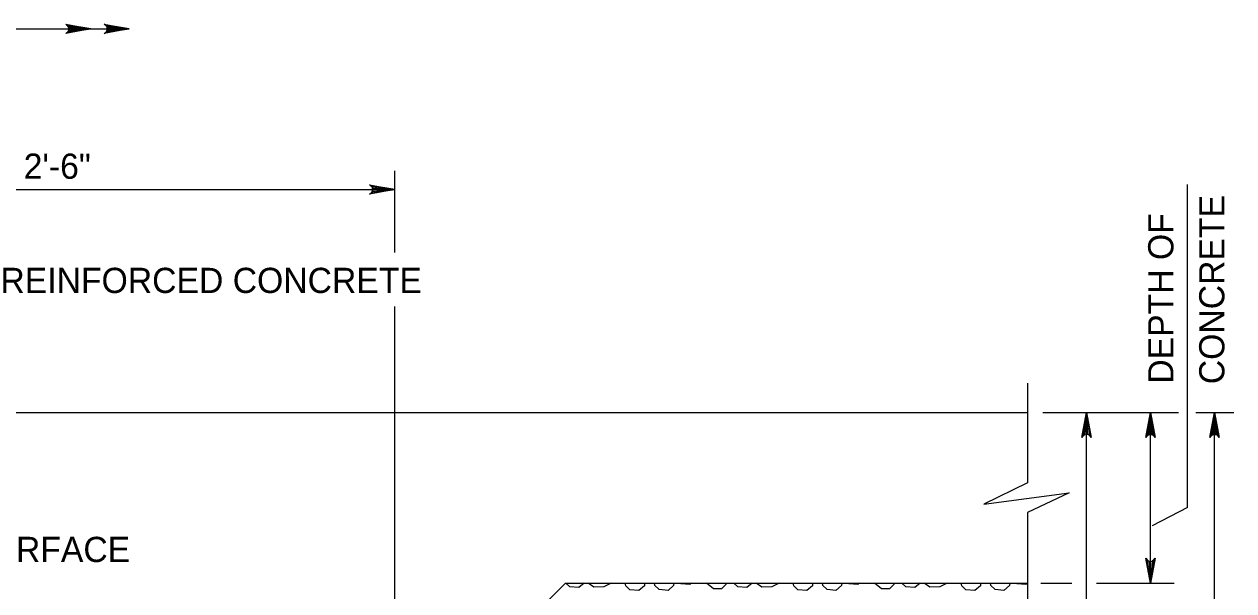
# Model space of a CAD drawing. Extents: x 638079 to 640019, y 297691 to 298879.
# Drawn here: x 639404.5 to 639548.5, y 298555.9 to 298623.3 of the extents above; entities that cross this region are included whole.
import ezdxf

# ---------------------------------------------------------------- set-up
doc = ezdxf.new("R2010")
doc.units = 0
doc.layers.add('1', color=7, linetype='Continuous')

msp = doc.modelspace()

# ---------------------------------------------------------------- linework, layer by layer
at = {"layer": '1'}
for p, q in [((639341.94, 298622.76), (639417.03, 298622.76)), ((639448.62, 298596.16), (639448.62, 298605.88)), ((639542.96, 298565.79), (639542.96, 298604.23)), ((639265.74, 298603.66), (639448.62, 298603.66)), ((639448.62, 298539.46), (639448.62, 298589.72)), ((639523.91, 298580.62), (639523.91, 298568.73)), ((639341.94, 298577.12), (639523.91, 298577.12)), ((639525.72, 298577.12), (639541.89, 298577.12)), ((639530.92, 298533.94), (639530.92, 298577.12)), ((639538.54, 298556.8), (639538.54, 298577.12)), ((639543.95, 298577.12), (639548.46, 298577.12)), ((639546.16, 298506), (639546.16, 298577.12)), ((639523.91, 298565.21), (639523.91, 298531.8)), ((639542.96, 298565.79), (639538.73, 298563.63)), ((639448.62, 298536.49), (639468.94, 298556.8)), ((639468.94, 298556.8), (639523.92, 298556.8)), ((639525.48, 298556.8), (639529.18, 298556.8)), ((639532.13, 298556.8), (639541.36, 298556.8))]:
    msp.add_line(p, q, dxfattribs=at)
for points in [[(639412.46, 298622.76), (639409.48, 298622.2), (639409.59, 298622.28), (639409.71, 298622.36), (639409.77, 298622.46), (639409.83, 298622.56), (639409.84, 298622.66), (639409.86, 298622.76), (639409.84, 298622.86), (639409.83, 298622.96), (639409.77, 298623.06), (639409.71, 298623.16), (639409.59, 298623.24), (639409.48, 298623.32), (639412.46, 298622.76), (639409.59, 298623.24), (639409.71, 298623.16), (639412.46, 298622.76), (639409.77, 298623.06), (639409.83, 298622.96), (639412.46, 298622.76), (639409.84, 298622.86), (639409.86, 298622.76), (639412.46, 298622.76), (639409.84, 298622.66), (639409.83, 298622.56), (639412.46, 298622.76), (639409.77, 298622.46), (639409.71, 298622.36), (639412.46, 298622.76), (639409.59, 298622.28)], [(639417.03, 298622.76), (639414.05, 298622.2), (639414.17, 298622.28), (639414.28, 298622.36), (639414.34, 298622.46), (639414.4, 298622.56), (639414.42, 298622.66), (639414.43, 298622.76), (639414.42, 298622.86), (639414.4, 298622.96), (639414.34, 298623.06), (639414.28, 298623.16), (639414.17, 298623.24), (639414.05, 298623.32), (639417.03, 298622.76), (639414.17, 298623.24), (639414.28, 298623.16), (639417.03, 298622.76), (639414.34, 298623.06), (639414.4, 298622.96), (639417.03, 298622.76), (639414.42, 298622.86), (639414.43, 298622.76), (639417.03, 298622.76), (639414.42, 298622.66), (639414.4, 298622.56), (639417.03, 298622.76), (639414.34, 298622.46), (639414.28, 298622.36), (639417.03, 298622.76), (639414.17, 298622.28)], [(639448.62, 298603.66), (639445.64, 298603.1), (639445.75, 298603.18), (639445.87, 298603.26), (639445.93, 298603.36), (639445.99, 298603.46), (639446, 298603.56), (639446.02, 298603.66), (639446, 298603.76), (639445.99, 298603.86), (639445.93, 298603.96), (639445.87, 298604.06), (639445.75, 298604.14), (639445.64, 298604.22), (639448.62, 298603.66), (639445.75, 298604.14), (639445.87, 298604.06), (639448.62, 298603.66), (639445.93, 298603.96), (639445.99, 298603.86), (639448.62, 298603.66), (639446, 298603.76), (639446.02, 298603.66), (639448.62, 298603.66), (639446, 298603.56), (639445.99, 298603.46), (639448.62, 298603.66), (639445.93, 298603.36), (639445.87, 298603.26), (639448.62, 298603.66), (639445.75, 298603.18)], [(639530.92, 298577.12), (639531.48, 298574.14), (639531.32, 298574.37), (639531.12, 298574.49), (639530.92, 298574.52), (639530.72, 298574.49), (639530.52, 298574.37), (639530.37, 298574.14), (639530.92, 298577.12), (639530.52, 298574.37), (639530.72, 298574.49), (639530.92, 298577.12), (639530.92, 298574.52), (639531.12, 298574.49), (639530.92, 298577.12), (639531.32, 298574.37)], [(639538.54, 298577.12), (639539.1, 298574.14), (639539.02, 298574.25), (639538.94, 298574.37), (639538.84, 298574.43), (639538.74, 298574.49), (639538.64, 298574.5), (639538.54, 298574.52), (639538.44, 298574.5), (639538.34, 298574.49), (639538.24, 298574.43), (639538.14, 298574.37), (639538.06, 298574.25), (639537.99, 298574.14), (639538.54, 298577.12), (639538.06, 298574.25), (639538.14, 298574.37), (639538.54, 298577.12), (639538.24, 298574.43), (639538.34, 298574.49), (639538.54, 298577.12), (639538.44, 298574.5), (639538.54, 298574.52), (639538.54, 298577.12), (639538.64, 298574.5), (639538.74, 298574.49), (639538.54, 298577.12), (639538.84, 298574.43), (639538.94, 298574.37), (639538.54, 298577.12), (639539.02, 298574.25)], [(639546.16, 298577.12), (639546.72, 298574.14), (639546.64, 298574.25), (639546.56, 298574.37), (639546.46, 298574.43), (639546.36, 298574.49), (639546.26, 298574.5), (639546.16, 298574.52), (639546.06, 298574.5), (639545.96, 298574.49), (639545.86, 298574.43), (639545.76, 298574.37), (639545.68, 298574.25), (639545.61, 298574.14), (639546.16, 298577.12), (639545.68, 298574.25), (639545.76, 298574.37), (639546.16, 298577.12), (639545.86, 298574.43), (639545.96, 298574.49), (639546.16, 298577.12), (639546.06, 298574.5), (639546.16, 298574.52), (639546.16, 298577.12), (639546.26, 298574.5), (639546.36, 298574.49), (639546.16, 298577.12), (639546.46, 298574.43), (639546.56, 298574.37), (639546.16, 298577.12), (639546.64, 298574.25)], [(639523.91, 298568.73), (639518.73, 298566.19), (639528.88, 298567.57), (639523.91, 298565.21)], [(639538.54, 298556.8), (639537.99, 298559.79), (639538.14, 298559.56), (639538.34, 298559.44), (639538.54, 298559.4), (639538.74, 298559.44), (639538.94, 298559.56), (639539.1, 298559.79), (639538.54, 298556.8), (639538.94, 298559.56), (639538.74, 298559.44), (639538.54, 298556.8), (639538.54, 298559.4), (639538.34, 298559.44), (639538.54, 298556.8), (639538.14, 298559.56)], [(639471.17, 298556.8), (639470.53, 298556.27), (639469.47, 298556.35), (639469, 298556.8)], [(639474.39, 298556.8), (639473.51, 298556.37), (639472.3, 298556.34), (639471.65, 298556.8)], [(639478.36, 298556.8), (639478.33, 298556.47), (639477.67, 298555.92), (639476.61, 298555.99), (639476.11, 298556.48), (639476.05, 298556.8)], [(639481.83, 298556.8), (639481.8, 298556.51), (639481.14, 298555.95), (639480.08, 298556.03), (639479.58, 298556.52), (639479.52, 298556.8)], [(639483.92, 298556.8), (639483.74, 298556.66), (639482.68, 298556.73), (639482.61, 298556.8)], [(639488.04, 298556.8), (639488.03, 298556.66), (639487.51, 298556.11), (639486.57, 298556.13), (639485.71, 298556.8)], [(639491.16, 298556.8), (639490.52, 298556.27), (639489.46, 298556.35), (639488.99, 298556.8)], [(639494.38, 298556.8), (639493.5, 298556.37), (639492.29, 298556.34), (639491.64, 298556.8)], [(639498.35, 298556.8), (639498.32, 298556.47), (639497.66, 298555.92), (639496.6, 298555.99), (639496.1, 298556.48), (639496.03, 298556.8)], [(639501.82, 298556.8), (639501.79, 298556.51), (639501.12, 298555.95), (639500.06, 298556.03), (639499.57, 298556.52), (639499.51, 298556.8)], [(639503.91, 298556.8), (639503.73, 298556.66), (639502.67, 298556.73), (639502.6, 298556.8)], [(639508.03, 298556.8), (639508.02, 298556.66), (639507.5, 298556.11), (639506.56, 298556.13), (639505.7, 298556.8)], [(639511.15, 298556.8), (639510.51, 298556.27), (639509.45, 298556.35), (639508.98, 298556.8)], [(639514.36, 298556.8), (639513.49, 298556.37), (639512.28, 298556.34), (639511.63, 298556.8)], [(639518.34, 298556.8), (639518.31, 298556.47), (639517.64, 298555.92), (639516.58, 298555.99), (639516.09, 298556.48), (639516.02, 298556.8)], [(639521.81, 298556.8), (639521.78, 298556.51), (639521.11, 298555.95), (639520.05, 298556.03), (639519.55, 298556.52), (639519.5, 298556.8)], [(639523.9, 298556.8), (639523.72, 298556.66), (639522.66, 298556.73), (639522.59, 298556.8)]]:
    msp.add_lwpolyline(points, dxfattribs=at)

# ---------------------------------------------------------------- texts
for s, p in [('2\'-6"', (639404.48, 298604.92)), ('REINFORCED CONCRETE', (639401.71, 298591.33)), ('SLIDING SURFACE', (639380.82, 298559.32))]:
    msp.add_text(s, height=3, dxfattribs=at).set_placement(p)
for s, p in [('CONCRETE', (639547.34, 298580.48)), ('DEPTH OF', (639541.27, 298580.54))]:
    msp.add_text(s, height=3, rotation=90, dxfattribs=at).set_placement(p)

doc.saveas('drawing.dxf')
